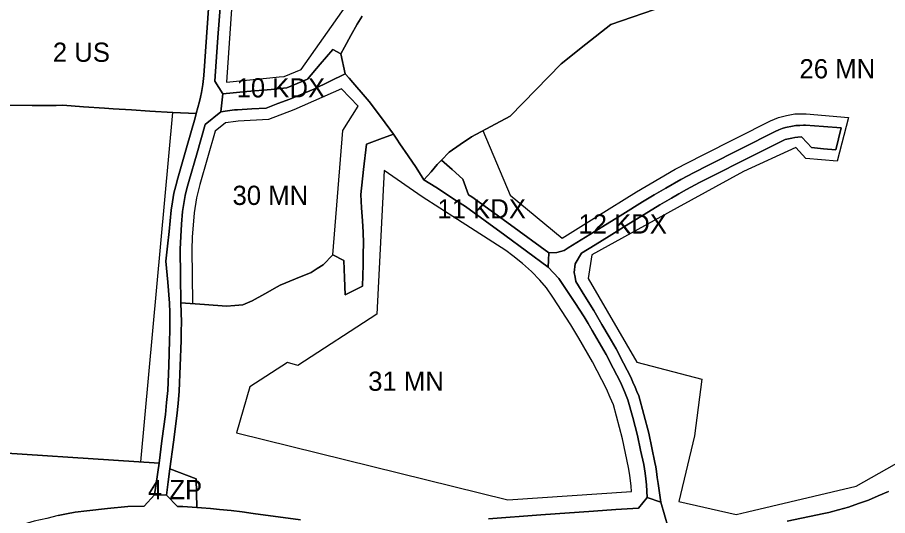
# Model space of a CAD drawing. Extents: x -294445 to -292055, y 21869 to 23693.
# Drawn here: x -292845.3 to -292392.4, y 22929.3 to 23188.4 of the extents above; entities that cross this region are included whole.
import ezdxf

# ---------------------------------------------------------------- set-up
doc = ezdxf.new("R2010")
doc.units = 0
for name, color, linetype in [('linie_rozgraniczajace', 7, 'Continuous'), ('linie_zabudowy_nieprzekraczalne', 7, 'Continuous'), ('oznaczenia_przeznaczen', 7, 'Continuous')]:
    doc.layers.add(name, color=color, linetype=linetype)

msp = doc.modelspace()

# ---------------------------------------------------------------- linework, layer by layer
at = {"layer": 'linie_rozgraniczajace'}
for points in [[(-292745.475, 23198.154), (-292746.897, 23178.216), (-292748.319, 23158.277), (-292748.758, 23153.518), (-292749.145, 23151.404), (-292749.531, 23149.291), (-292750.032, 23146.97), (-292750.534, 23144.649), (-292752.22, 23138.36), (-292764.315, 23139.005), (-292776.41, 23139.65), (-292785.93, 23140.3), (-292795.45, 23140.95), (-292800, 23141.25), (-292810.81, 23141.97), (-292821.62, 23142.69), (-292825.15, 23142.67), (-292831.415, 23142.63), (-292837.68, 23142.59), (-292854.505, 23142.855)], [(-292759.99, 23025.09), (-292760.072, 23020.268), (-292760.571, 23007.086), (-292761.07, 22993.905), (-292761.667, 22987.563), (-292762.263, 22981.222), (-292764.092, 22967.431), (-292765.92, 22953.64), (-292766.827, 22946.802), (-292767.733, 22939.964), (-292773.918, 22939.989), (-292771.589, 22956.531), (-292770.047, 22968.163), (-292768.226, 22981.897), (-292767.643, 22988.099), (-292767.059, 22994.3), (-292766.565, 23007.366), (-292766.07, 23020.432), (-292765.99, 23025.158), (-292765.91, 23029.884), (-292766.04, 23034.856), (-292766.169, 23039.827), (-292767.074, 23050.764), (-292767.98, 23061.7), (-292767.184, 23069.35), (-292766.389, 23077), (-292765.826, 23082.547), (-292765.264, 23088.095), (-292764.56, 23092.523), (-292763.857, 23096.952), (-292762.867, 23100.834), (-292761.877, 23104.716), (-292757.329, 23120.492), (-292752.781, 23136.268), (-292752.22, 23138.36), (-292750.534, 23144.649), (-292750.032, 23146.97), (-292749.531, 23149.291), (-292749.145, 23151.404), (-292748.758, 23153.518), (-292748.319, 23158.277), (-292746.897, 23178.216), (-292745.475, 23198.154)], [(-292739.47, 23198.01), (-292740.904, 23177.899), (-292742.338, 23157.788), (-292742.58, 23155.171), (-292738.298, 23148.599), (-292739.502, 23139.319), (-292747.557, 23132.729), (-292751.821, 23117.936), (-292756.086, 23103.143), (-292757.03, 23099.44), (-292757.974, 23095.737), (-292758.637, 23091.563), (-292759.301, 23087.389), (-292759.808, 23080.912), (-292760.314, 23074.436), (-292760.45, 23071.112), (-292760.585, 23067.788), (-292760.377, 23053.869), (-292760.17, 23039.95), (-292760.04, 23034.931), (-292759.909, 23029.912), (-292759.99, 23025.09)], [(-292665.825, 23189.025), (-292668.42, 23184.95), (-292671.708, 23178.975), (-292674.997, 23173), (-292676.89, 23169.56), (-292681.197, 23171.767), (-292687.719, 23164.038), (-292694.24, 23156.31), (-292699.645, 23154.05), (-292705.05, 23151.79), (-292706.781, 23151.624), (-292708.513, 23151.458), (-292713.304, 23150.998), (-292725.801, 23149.798), (-292738.298, 23148.599), (-292742.58, 23155.171), (-292742.338, 23157.788), (-292740.904, 23177.899), (-292739.47, 23198.01)], [(-292508.135, 23194.48), (-292536.51, 23184.74), (-292549.385, 23174.54), (-292562.26, 23164.34), (-292575.53, 23150.695), (-292588.8, 23137.05), (-292598.915, 23131.695), (-292609.03, 23126.34), (-292614.805, 23122.315), (-292620.58, 23118.29), (-292624.51, 23114.208), (-292626.79, 23111.84), (-292629.97, 23108.03), (-292633.72, 23104), (-292637.81, 23110.29), (-292641.994, 23116.458), (-292646.178, 23122.626), (-292647.889, 23125.148), (-292649.6, 23127.67), (-292655.865, 23136.155), (-292662.13, 23144.64), (-292665.403, 23148.392), (-292669.685, 23153.334), (-292670.693, 23154.523), (-292672.71, 23156.801), (-292674.698, 23159.048), (-292676.89, 23169.56)], [(-292624.51, 23114.208), (-292620.58, 23118.29), (-292614.805, 23122.315), (-292609.03, 23126.34), (-292598.915, 23131.695), (-292588.8, 23137.05), (-292575.53, 23150.695), (-292562.26, 23164.34), (-292549.385, 23174.54), (-292536.51, 23184.74), (-292508.135, 23194.48)], [(-292676.89, 23169.56), (-292674.997, 23173), (-292671.708, 23178.975), (-292668.42, 23184.95), (-292665.825, 23189.025)], [(-292837.68, 23142.59), (-292831.415, 23142.63), (-292825.15, 23142.67), (-292821.62, 23142.69), (-292810.81, 23141.97), (-292800, 23141.25), (-292795.45, 23140.95), (-292785.93, 23140.3), (-292776.41, 23139.65), (-292764.315, 23139.005), (-292752.22, 23138.36), (-292752.781, 23136.268), (-292757.329, 23120.492), (-292761.877, 23104.716), (-292762.867, 23100.834), (-292763.857, 23096.952), (-292764.56, 23092.523), (-292765.264, 23088.095), (-292765.826, 23082.547), (-292766.389, 23077), (-292767.184, 23069.35), (-292767.98, 23061.7), (-292767.074, 23050.764), (-292766.169, 23039.827), (-292766.04, 23034.856), (-292765.91, 23029.884), (-292765.99, 23025.158), (-292766.07, 23020.432), (-292766.565, 23007.366), (-292767.059, 22994.3), (-292767.643, 22988.099), (-292768.226, 22981.897), (-292770.047, 22968.163), (-292771.589, 22956.531), (-292877.28, 22963.509)], [(-292854.505, 23142.855), (-292837.68, 23142.59)], [(-292435.08, 23132.322), (-292436.188, 23132.338), (-292438.128, 23132.275), (-292440.068, 23132.212), (-292441.919, 23131.872), (-292445.513, 23131.107), (-292447.257, 23130.684), (-292449.046, 23129.916), (-292450.835, 23129.149), (-292468.419, 23120.292), (-292486.002, 23111.435), (-292493.003, 23107.79), (-292500.004, 23104.145), (-292507.883, 23099.652), (-292513.919, 23096.076), (-292519.955, 23092.5), (-292530.252, 23086.095), (-292540.55, 23079.69), (-292549.553, 23074.089), (-292558.556, 23068.488), (-292560.768, 23067.112), (-292564.597, 23066.178), (-292568.637, 23065.909), (-292588.694, 23080.494), (-292608.751, 23095.078), (-292610.501, 23096.169), (-292613.491, 23104.348), (-292619.001, 23109.278), (-292624.51, 23114.208)], [(-292569.009, 23058.498), (-292568.823, 23062.204), (-292568.637, 23065.909), (-292564.597, 23066.178), (-292560.768, 23067.112), (-292558.556, 23068.488), (-292549.553, 23074.089), (-292540.55, 23079.69), (-292530.252, 23086.095), (-292519.955, 23092.5), (-292513.919, 23096.076), (-292507.883, 23099.652), (-292500.004, 23104.145), (-292493.003, 23107.79), (-292486.002, 23111.435), (-292468.419, 23120.292), (-292450.835, 23129.149), (-292449.046, 23129.916), (-292447.257, 23130.684), (-292445.513, 23131.107), (-292441.919, 23131.872), (-292440.068, 23132.212), (-292438.128, 23132.275), (-292436.188, 23132.338), (-292435.08, 23132.322), (-292425.781, 23131.617), (-292416.482, 23130.912), (-292417.915, 23125.208), (-292419.348, 23119.504), (-292425.678, 23120.108), (-292432.008, 23120.713), (-292434.314, 23123.211), (-292437.125, 23126.285), (-292439.066, 23126.189), (-292440.637, 23125.931), (-292442.209, 23125.673), (-292445.696, 23124.825), (-292449.14, 23123.258), (-292466.221, 23114.667), (-292483.303, 23106.076), (-292490.217, 23102.476), (-292497.132, 23098.877), (-292500.999, 23096.671), (-292504.867, 23094.464), (-292510.882, 23090.901), (-292516.897, 23087.338), (-292527.139, 23080.967), (-292537.381, 23074.595), (-292544.544, 23070.146), (-292551.707, 23065.697), (-292554.92, 23060.208), (-292555.476, 23055.688), (-292555.044, 23053.324), (-292554.612, 23050.961), (-292549.946, 23043.42), (-292545.28, 23035.88), (-292543.165, 23032.255), (-292541.05, 23028.63), (-292537.35, 23022.305), (-292533.65, 23015.98), (-292529.825, 23008.62), (-292526, 23001.26), (-292524.91, 22998.7), (-292523.82, 22996.14), (-292522.83, 22993.81), (-292521.84, 22991.48), (-292519.262, 22981.853), (-292516.685, 22972.227), (-292515.067, 22964.572), (-292513.448, 22956.918), (-292513.041, 22954.593), (-292512.633, 22952.268), (-292512.247, 22949.095), (-292511.862, 22945.922), (-292511.114, 22941.081), (-292510.365, 22936.24), (-292517.507, 22938.604), (-292517.665, 22941.92), (-292517.822, 22945.236), (-292518.196, 22948.311), (-292518.57, 22951.387), (-292518.955, 22953.583), (-292519.34, 22955.779), (-292520.948, 22963.382), (-292522.555, 22970.986), (-292525.041, 22980.253), (-292527.526, 22989.52), (-292529.342, 22993.794), (-292530.386, 22996.246), (-292531.43, 22998.698), (-292535.167, 23005.889), (-292538.905, 23013.08), (-292542.568, 23019.342), (-292546.231, 23025.603), (-292548.307, 23029.162), (-292550.383, 23032.721), (-292555.179, 23040.035), (-292559.975, 23047.349), (-292563.583, 23052.545)], [(-292506.657, 22923.115), (-292510.365, 22936.24), (-292511.114, 22941.081), (-292511.862, 22945.922), (-292512.247, 22949.095), (-292512.633, 22952.268), (-292513.041, 22954.593), (-292513.448, 22956.918), (-292515.067, 22964.572), (-292516.685, 22972.227), (-292519.262, 22981.853), (-292521.84, 22991.48), (-292522.83, 22993.81), (-292523.82, 22996.14), (-292524.91, 22998.7), (-292526, 23001.26), (-292529.825, 23008.62), (-292533.65, 23015.98), (-292537.35, 23022.305), (-292541.05, 23028.63), (-292543.165, 23032.255), (-292545.28, 23035.88), (-292549.946, 23043.42), (-292554.612, 23050.961), (-292555.044, 23053.324), (-292555.476, 23055.688), (-292554.92, 23060.208), (-292551.707, 23065.697), (-292544.544, 23070.146), (-292537.381, 23074.595), (-292527.139, 23080.967), (-292516.897, 23087.338), (-292510.882, 23090.901), (-292504.867, 23094.464), (-292500.999, 23096.671), (-292497.132, 23098.877), (-292490.217, 23102.476), (-292483.303, 23106.076), (-292466.221, 23114.667), (-292449.14, 23123.258), (-292445.696, 23124.825), (-292442.209, 23125.673), (-292440.637, 23125.931), (-292439.066, 23126.189), (-292437.125, 23126.285), (-292434.314, 23123.211), (-292432.008, 23120.713), (-292425.678, 23120.108), (-292419.348, 23119.504), (-292417.915, 23125.208), (-292416.482, 23130.912), (-292425.781, 23131.617), (-292435.08, 23132.322)], [(-292697.936, 22927.017), (-292722.573, 22930.405), (-292728.269, 22931.132), (-292733.965, 22931.858), (-292740.174, 22932.43), (-292744.809, 22932.891), (-292749.444, 22933.351), (-292751.832, 22933.491), (-292752.192, 22948.465), (-292765.92, 22953.64), (-292764.092, 22967.431), (-292762.263, 22981.222), (-292761.667, 22987.563), (-292761.07, 22993.905), (-292760.571, 23007.086), (-292760.072, 23020.268), (-292759.99, 23025.09), (-292759.909, 23029.912), (-292760.04, 23034.931), (-292760.17, 23039.95), (-292747.935, 23039.025), (-292736.4, 23038.15), (-292732.215, 23038.56), (-292728.03, 23038.97), (-292725.53, 23040), (-292723.03, 23041.03), (-292716.6, 23044.64), (-292710.17, 23048.25), (-292708.53, 23049.17), (-292700.485, 23052.475), (-292692.44, 23055.78), (-292689.27, 23057.73), (-292686.1, 23059.68), (-292681.09, 23064.99), (-292675.39, 23061.94), (-292675.08, 23052.98), (-292674.77, 23044.02), (-292670.25, 23046.28), (-292665.73, 23048.54), (-292665.573, 23054.133), (-292665.415, 23059.725), (-292665.258, 23065.318), (-292665.1, 23070.91), (-292665.407, 23076.76), (-292665.715, 23082.61), (-292666.172, 23089.425), (-292666.63, 23096.24), (-292665.1, 23109.375), (-292663.57, 23122.51), (-292656.585, 23125.09), (-292649.6, 23127.67), (-292647.889, 23125.148), (-292646.178, 23122.626), (-292641.994, 23116.458), (-292637.81, 23110.29), (-292633.72, 23104), (-292627.577, 23100.05), (-292616.713, 23093.065), (-292611.991, 23090.029), (-292601.83, 23082.625), (-292591.669, 23075.222), (-292580.339, 23066.86), (-292569.009, 23058.498), (-292566.296, 23055.521), (-292563.583, 23052.545), (-292559.975, 23047.349), (-292555.179, 23040.035), (-292550.383, 23032.721), (-292548.307, 23029.162), (-292546.231, 23025.603), (-292542.568, 23019.342), (-292538.905, 23013.08), (-292535.167, 23005.889), (-292531.43, 22998.698), (-292530.386, 22996.246), (-292529.342, 22993.794), (-292527.526, 22989.52), (-292525.041, 22980.253), (-292522.555, 22970.986), (-292520.948, 22963.382), (-292519.34, 22955.779), (-292518.955, 22953.583), (-292518.57, 22951.387), (-292518.196, 22948.311), (-292517.822, 22945.236), (-292517.665, 22941.92), (-292517.507, 22938.604), (-292522.029, 22933.174), (-292533.759, 22932.382), (-292545.49, 22931.59), (-292572.832, 22929.622), (-292600.173, 22927.654)], [(-292563.583, 23052.545), (-292566.296, 23055.521), (-292569.009, 23058.498)], [(-292877.28, 22963.509), (-292771.589, 22956.531), (-292773.918, 22939.989), (-292779.321, 22934.119), (-292787.762, 22933.952), (-292798.439, 22932.873), (-292809.117, 22931.794), (-292815.239, 22931.067), (-292819.688, 22930.162), (-292824.138, 22929.257), (-292829.968, 22927.793), (-292833.288, 22927.089), (-292836.609, 22926.385), (-292845.246, 22923.759), (-292851.578, 22924.027)], [(-292391.99, 22941.853), (-292397.229, 22939.543), (-292402.408, 22937.268), (-292407.552, 22935.485), (-292412.696, 22933.703), (-292417.869, 22932.329), (-292423.041, 22930.955), (-292425.606, 22930.273), (-292444.67, 22926.318)], [(-292444.67, 22926.318), (-292425.606, 22930.273), (-292423.041, 22930.955), (-292417.869, 22932.329), (-292412.696, 22933.703), (-292407.552, 22935.485), (-292402.408, 22937.268), (-292397.229, 22939.543), (-292391.99, 22941.853)], [(-292824.138, 22929.257), (-292819.688, 22930.162), (-292815.239, 22931.067), (-292809.117, 22931.794), (-292798.439, 22932.873), (-292787.762, 22933.952), (-292779.321, 22934.119), (-292773.918, 22939.989), (-292767.733, 22939.964), (-292762.036, 22933.936), (-292759.208, 22933.923), (-292751.832, 22933.491), (-292749.444, 22933.351), (-292744.809, 22932.891), (-292740.174, 22932.43), (-292733.965, 22931.858), (-292728.269, 22931.132), (-292722.573, 22930.405), (-292697.936, 22927.017)], [(-292600.173, 22927.654), (-292572.832, 22929.622), (-292545.49, 22931.59), (-292533.759, 22932.382), (-292522.029, 22933.174), (-292517.507, 22938.604), (-292510.365, 22936.24), (-292506.657, 22923.115)]]:
    msp.add_lwpolyline(points, dxfattribs=at)
for points in [[(-292739.502, 23139.319), (-292738.298, 23148.599), (-292725.801, 23149.798), (-292713.304, 23150.998), (-292708.513, 23151.458), (-292706.781, 23151.624), (-292705.05, 23151.79), (-292699.645, 23154.05), (-292694.24, 23156.31), (-292687.719, 23164.038), (-292681.197, 23171.767), (-292676.89, 23169.56), (-292674.698, 23159.048), (-292682.871, 23155.095), (-292691.043, 23151.143), (-292697.308, 23148.524), (-292703.573, 23145.904), (-292709.722, 23143.597), (-292715.87, 23141.29), (-292723.32, 23140.84), (-292730.77, 23140.39), (-292732.25, 23140.3), (-292735.876, 23139.81)], [(-292760.585, 23067.788), (-292760.45, 23071.112), (-292760.314, 23074.436), (-292759.808, 23080.912), (-292759.301, 23087.389), (-292758.637, 23091.563), (-292757.974, 23095.737), (-292757.03, 23099.44), (-292756.086, 23103.143), (-292751.821, 23117.936), (-292747.557, 23132.729), (-292739.502, 23139.319), (-292735.876, 23139.81), (-292732.25, 23140.3), (-292730.77, 23140.39), (-292723.32, 23140.84), (-292715.87, 23141.29), (-292709.722, 23143.597), (-292703.573, 23145.904), (-292697.308, 23148.524), (-292691.043, 23151.143), (-292682.871, 23155.095), (-292674.698, 23159.048), (-292672.71, 23156.801), (-292670.693, 23154.523), (-292669.685, 23153.334), (-292665.403, 23148.392), (-292662.13, 23144.64), (-292655.865, 23136.155), (-292649.6, 23127.67), (-292656.585, 23125.09), (-292663.57, 23122.51), (-292665.1, 23109.375), (-292666.63, 23096.24), (-292666.172, 23089.425), (-292665.715, 23082.61), (-292665.407, 23076.76), (-292665.1, 23070.91), (-292665.258, 23065.318), (-292665.415, 23059.725), (-292665.573, 23054.133), (-292665.73, 23048.54), (-292670.25, 23046.28), (-292674.77, 23044.02), (-292675.08, 23052.98), (-292675.39, 23061.94), (-292681.09, 23064.99), (-292686.1, 23059.68), (-292689.27, 23057.73), (-292692.44, 23055.78), (-292700.485, 23052.475), (-292708.53, 23049.17), (-292710.17, 23048.25), (-292716.6, 23044.64), (-292723.03, 23041.03), (-292725.53, 23040), (-292728.03, 23038.97), (-292732.215, 23038.56), (-292736.4, 23038.15), (-292747.935, 23039.025), (-292760.17, 23039.95), (-292760.377, 23053.869)], [(-292633.72, 23104), (-292629.97, 23108.03), (-292626.79, 23111.84), (-292624.51, 23114.208), (-292619.001, 23109.278), (-292613.491, 23104.348), (-292610.501, 23096.169), (-292608.751, 23095.078), (-292588.694, 23080.494), (-292568.637, 23065.909), (-292568.823, 23062.204), (-292569.009, 23058.498), (-292580.339, 23066.86), (-292591.669, 23075.222), (-292601.83, 23082.625), (-292611.991, 23090.029), (-292616.713, 23093.065), (-292627.577, 23100.05)], [(-292767.733, 22939.964), (-292766.827, 22946.802), (-292765.92, 22953.64), (-292752.192, 22948.465), (-292751.832, 22933.491), (-292759.208, 22933.923), (-292762.036, 22933.936)]]:
    msp.add_lwpolyline(points, close=True, dxfattribs=at)
at = {"layer": 'linie_zabudowy_nieprzekraczalne'}
for points in [[(-292733.465, 23197.866), (-292736.358, 23157.298), (-292736.445, 23154.804), (-292713.877, 23156.97), (-292709.086, 23157.43), (-292706.527, 23157.676), (-292697.661, 23161.383), (-292697.661, 23161.383), (-292697.661, 23161.383), (-292662.763, 23210.924)], [(-292681.09, 23064.99), (-292675.961, 23129.609), (-292667.984, 23142.257), (-292676.573, 23151.228), (-292701.361, 23140.326), (-292714.607, 23135.355), (-292730.407, 23134.401), (-292731.665, 23134.324), (-292737.016, 23133.601), (-292742.31, 23129.27), (-292750.295, 23101.571), (-292752.092, 23094.523), (-292753.338, 23086.683), (-292754.324, 23074.08), (-292754.583, 23067.711), (-292754.171, 23040.073), (-292754.156, 23039.497)], [(-292781.105, 22957.159), (-292764.441, 23139.012)], [(-292603.006, 23129.529), (-292588.754, 23095.926), (-292561.726, 23073.583), (-292561.726, 23073.583), (-292543.719, 23084.785), (-292523.069, 23097.63), (-292510.899, 23104.839), (-292502.877, 23109.414), (-292488.737, 23116.775), (-292453.37, 23134.59), (-292449.161, 23136.396), (-292445.022, 23137.401), (-292440.712, 23138.195), (-292436.244, 23138.339), (-292434.811, 23138.319), (-292412.705, 23136.379), (-292418.584, 23113.702), (-292434.862, 23114.958), (-292440.18, 23120.832), (-292440.18, 23120.832), (-292440.18, 23120.832), (-292440.18, 23120.832), (-292467.33, 23108.26), (-292467.33, 23108.26), (-292501.852, 23089.277), (-292546.288, 23064.966), (-292546.288, 23064.966), (-292546.288, 23064.966), (-292548.23, 23052.67), (-292522.895, 23009.043), (-292522.895, 23009.043), (-292489.025, 23000.173), (-292492.893, 22970.733), (-292501.019, 22936.517), (-292471.223, 22929.752), (-292465.225, 22931.298), (-292408.656, 22944.635), (-292384.858, 22958.166)], [(-292731.226, 22972.273), (-292590.061, 22937.415), (-292525.656, 22941.72), (-292525.799, 22944.563), (-292526.486, 22950.213), (-292527.196, 22954.259), (-292530.338, 22969.121), (-292535.108, 22986.907), (-292536.704, 22990.662), (-292538.67, 22995.281), (-292545.911, 23009.213), (-292553.138, 23021.568), (-292557.188, 23028.509), (-292566.607, 23042.874), (-292569.94, 23047.673), (-292573.386, 23051.758), (-292577.766, 23056.161), (-292582.458, 23060.428), (-292587.478, 23064.45), (-292591.094, 23067.146), (-292616.312, 23083.296), (-292634.561, 23095.03), (-292654.383, 23108.808), (-292658.165, 23034.02), (-292699.367, 23007.365), (-292704.762, 23008.828), (-292724.328, 22996.21), (-292731.226, 22972.273)]]:
    msp.add_lwpolyline(points, dxfattribs=at)

# ---------------------------------------------------------------- texts
at = {"layer": 'oznaczenia_przeznaczen'}
for s, p in [('2 US', (-292826.858, 23165.318)), ('26 MN', (-292438.238, 23156.716)), ('10 KDX', (-292731.229, 23146.79)), ('30 MN', (-292733.344, 23090.862)), ('11 KDX', (-292626.694, 23083.822)), ('12 KDX', (-292553.318, 23075.967)), ('31 MN', (-292662.734, 22994.172)), ('4 ZP', (-292777.364, 22937.772))]:
    msp.add_text(s, height=10, dxfattribs=at).set_placement(p)

doc.saveas('drawing.dxf')
